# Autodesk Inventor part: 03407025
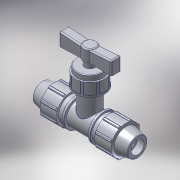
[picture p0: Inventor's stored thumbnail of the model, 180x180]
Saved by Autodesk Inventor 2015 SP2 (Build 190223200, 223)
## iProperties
Created: 2017-02
Part Number: 03407025
Material: PVC-Piping
Description: PLASSON COMPRESSION STOPTAP 25
Document SubType Name: Modeling
Designer: KIM
Mass: 92.6774 g
Surface Area: 199.44 cm^2
Volume: 66.1981 cm^3
Density: 1.4 g/cm^3
Appearance: PTFE
Author: KIM
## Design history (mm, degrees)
derived "03407.ipt"
feature "Solid1::03407.ipt"
tag "TaggingFeature1"
body "Solid1"
other parameters: "d1" = 154, "d2" = 25, "d4" = 12.83333, "d5" = 18.48, "d7" = 54, "d8" = 40.5, "d9" = 38.5, "d11" = 3.85, "d12" = 43.2, "d13" = 120 deg, "d14" = 37.5, "d15" = 12 deg, "d16" = 48.6, "d18" = 1.25, "d19" = 35 deg, "d20" = 17.5 deg, "d21" = 50.22, "d23" = 0, "d25" = 360 deg, "d27" = 1.08, "d33" = 0.5, "d42" = 27.72, "d43" = 1.62, "d46" = 0.75, "d49" = 49, "d51" = 91, "d53" = 18.2, "d54" = 18.2, "d57" = 16.38, "d60" = 40.95, "d61" = 27.3, "d62" = 18.2, "d63" = 59.15, "d64" = 14.56, "d65" = 36.4, "d66" = 7.28, "d69" = 12.285, "d70" = 6.1425, "d71" = 40.131, "d72" = 41.4, "d74" = 0, "d75" = 15.47, "d76" = 92, "d77" = 92, "d80" = 360 deg, "d82" = 0.364, "d85" = 36.4, "d86" = 6 deg, "d87" = 94 deg, "d88" = 13.65, "d89" = 0, "d90" = 2, "d91" = 2, "d92" = 0.91, "d93" = 0.91, "d_" = 25, "E_" = 54, "H_" = 154, "l_" = 49, "A_" = 91, "d67" = 92, "d78" = 40.95
